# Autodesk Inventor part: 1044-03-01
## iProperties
Created: 2007-03
Part Number: 1044-03-01
Document SubType Name: Modeling
Designer: Andy Moles
Material: Steel
Mass: 1.74773 g
Surface Area: 2.53336 cm^2
Volume: 0.222641 cm^3
Density: 7.85 g/cm^3
Author: Andy Moles
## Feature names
1. Base1
